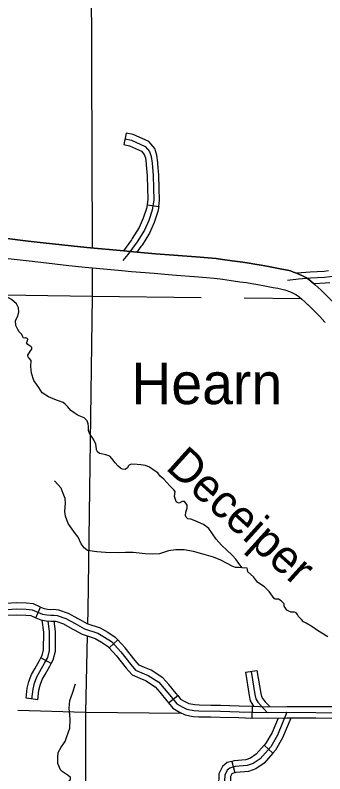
# Model space of a CAD drawing. Extents: x 813775 to 1157140, y 1757555 to 1979907.
# Drawn here: x 931113 to 939008, y 1842754 to 1862069 of the extents above; entities that cross this region are included whole.
import ezdxf

# ---------------------------------------------------------------- set-up
doc = ezdxf.new("R2010")
doc.units = 0
for name, color, linetype in [('Level 10', 7, 'Continuous'), ('Level 25', 7, 'Continuous'), ('Level 31', 7, 'Continuous'), ('Level 32', 7, 'Continuous'), ('Level 35', 7, 'Continuous'), ('Level 5', 7, 'Continuous')]:
    doc.layers.add(name, color=color, linetype=linetype)

msp = doc.modelspace()

# ---------------------------------------------------------------- linework, layer by layer
at = {"layer": 'Level 10'}
for p, q in [((938921, 1855062), (938925, 1855058)), ((938578, 1854698), (938573, 1854702)), ((939007, 1854249), (939009, 1854246))]:
    msp.add_line(p, q, dxfattribs=at)
for points in [[(930839, 1856390), (931449, 1856317), (931825, 1856276), (932539, 1856194), (932942, 1856153), (933881, 1856069), (934127, 1856042), (934695, 1855996), (935154, 1855959), (935828, 1855905), (936032, 1855891), (936236, 1855870), (936400, 1855851), (936643, 1855816), (936915, 1855778), (937082, 1855753), (937225, 1855731), (937384, 1855704), (937572, 1855672), (937782, 1855631), (937915, 1855605), (938054, 1855573), (938129, 1855557), (938206, 1855528), (938261, 1855509), (938345, 1855474), (938436, 1855434), (938519, 1855390), (938593, 1855344), (938663, 1855291), (938752, 1855216), (938832, 1855146), (938921, 1855062)], [(938921, 1855062), (938832, 1855146), (938752, 1855216), (938663, 1855291), (938593, 1855344), (938519, 1855390), (938436, 1855434), (938345, 1855474), (938261, 1855509), (938206, 1855528), (938129, 1855557), (938054, 1855573), (937915, 1855605), (937782, 1855631), (937572, 1855672), (937384, 1855704), (937225, 1855731), (937082, 1855753), (936915, 1855778), (936643, 1855816), (936400, 1855851), (936236, 1855870), (936032, 1855891), (935828, 1855905), (935154, 1855959), (934695, 1855996), (934127, 1856042), (933881, 1856069), (932942, 1856153), (932539, 1856194), (931825, 1856276), (931449, 1856317), (930839, 1856390)], [(930779, 1855894), (931393, 1855820), (931770, 1855779), (932485, 1855697), (932895, 1855655), (933831, 1855572), (934079, 1855544), (934655, 1855498), (935113, 1855461), (935791, 1855406), (935990, 1855392), (936183, 1855372), (936337, 1855355), (936573, 1855321), (936843, 1855283), (937007, 1855259), (937146, 1855237), (937301, 1855211), (937481, 1855181), (937687, 1855140), (937812, 1855116), (937946, 1855085), (937988, 1855076), (938035, 1855059), (938081, 1855042), (938147, 1855014), (938218, 1854983), (938269, 1854956), (938310, 1854931), (938350, 1854901), (938425, 1854837), (938496, 1854775), (938578, 1854698)], [(930779, 1855894), (931393, 1855820), (931770, 1855779), (932485, 1855697), (932895, 1855655), (933831, 1855572), (934079, 1855544), (934655, 1855498), (935113, 1855461), (935791, 1855406), (935990, 1855392), (936183, 1855372), (936337, 1855355), (936573, 1855321), (936843, 1855283), (937007, 1855259), (937146, 1855237), (937301, 1855211), (937481, 1855181), (937687, 1855140), (937812, 1855116), (937946, 1855085), (937988, 1855076), (938035, 1855059), (938081, 1855042), (938147, 1855014), (938218, 1854983), (938269, 1854956), (938310, 1854931), (938350, 1854901), (938425, 1854837), (938496, 1854775), (938578, 1854698)], [(938925, 1855058), (939060, 1854924), (939243, 1854735), (939380, 1854581)], [(939380, 1854581), (939243, 1854735), (939060, 1854924), (938925, 1855058)], [(938573, 1854702), (938704, 1854573), (938877, 1854395), (939007, 1854249)], [(938573, 1854702), (938704, 1854573), (938877, 1854395), (939007, 1854249)]]:
    msp.add_lwpolyline(points, dxfattribs=at)
at = {"layer": 'Level 31'}
for p, q in [((933945, 1859068), (933882, 1858775)), ((934475, 1857243), (934772, 1857198)), ((931642, 1846726), (931763, 1847001)), ((933729, 1846165), (933507, 1845962)), ((935023, 1844561), (935258, 1844747)), ((937154, 1844174), (937163, 1844474))]:
    msp.add_line(p, q, dxfattribs=at)
for points in [[(934754, 1858286), (934751, 1858316), (934727, 1858507), (934672, 1858676), (934522, 1858850), (934125, 1859029), (933945, 1859068)], [(933882, 1858775), (934031, 1858743), (934338, 1858604), (934405, 1858525), (934433, 1858441), (934453, 1858285), (934455, 1858261)], [(933914, 1858921), (934078, 1858886), (934430, 1858727), (934539, 1858600)], [(934539, 1858600), (934580, 1858474), (934602, 1858300), (934629, 1857985), (934637, 1857661), (934646, 1857372), (934606, 1857109), (934518, 1856843), (934407, 1856594), (934225, 1856301), (933985, 1855972), (933856, 1855821)], [(934455, 1858261), (934479, 1857977), (934488, 1857656), (934496, 1857381), (934475, 1857243)], [(934455, 1858261), (934479, 1857977), (934488, 1857656), (934496, 1857381), (934475, 1857243)], [(934772, 1857198), (934797, 1857363), (934787, 1857665), (934778, 1857993), (934754, 1858286)], [(934475, 1857243), (934460, 1857145), (934378, 1856897), (934274, 1856664), (934100, 1856384), (934077, 1856352)], [(934772, 1857198), (934753, 1857074), (934658, 1856788), (934539, 1856523), (934349, 1856217), (934319, 1856176)], [(934077, 1856352), (933871, 1856070)], [(934319, 1856176), (934216, 1856035)], [(939102, 1855556), (938990, 1855543), (938630, 1855527), (938292, 1855497)], [(939137, 1855258), (939014, 1855243), (938734, 1855231)], [(931763, 1847001), (931585, 1847079), (931406, 1847095), (931146, 1847104), (930887, 1847090), (930606, 1847025), (930571, 1846994)], [(931763, 1847001), (931852, 1846961), (931939, 1846947), (932025, 1846940), (932101, 1846944), (932219, 1846933), (932465, 1846847), (932712, 1846712), (932765, 1846683)], [(930748, 1846750), (930929, 1846792), (931149, 1846804), (931387, 1846795), (931510, 1846785), (931642, 1846726)], [(931642, 1846726), (931767, 1846671), (931902, 1846649), (932020, 1846639), (932095, 1846644), (932154, 1846638), (932343, 1846572), (932568, 1846449), (932621, 1846420)], [(932765, 1846683), (932944, 1846585), (933279, 1846474), (933474, 1846362), (933666, 1846233), (933729, 1846165)], [(932621, 1846420), (932824, 1846309), (933155, 1846199), (933315, 1846107), (933469, 1846004), (933507, 1845962)], [(934409, 1845464), (934274, 1845521), (934176, 1845637), (933917, 1845958), (933729, 1846165)], [(933507, 1845962), (933689, 1845763), (933945, 1845445), (934092, 1845273), (934292, 1845188)], [(935258, 1844747), (935215, 1844802), (935030, 1845027), (934877, 1845201), (934578, 1845392), (934409, 1845464)], [(934292, 1845188), (934437, 1845126), (934680, 1844971), (934802, 1844833), (934981, 1844614), (935023, 1844561)], [(935258, 1844747), (935331, 1844654), (935438, 1844592), (935540, 1844545), (935691, 1844515), (935806, 1844507), (936105, 1844502)], [(935023, 1844561), (935131, 1844424), (935299, 1844326), (935446, 1844258), (935651, 1844217), (935793, 1844207), (936100, 1844202)], [(936105, 1844502), (936349, 1844498), (936825, 1844485), (937163, 1844474)], [(937163, 1844474), (937541, 1844462), (938041, 1844471), (938215, 1844470)], [(938215, 1844470), (938783, 1844467), (939271, 1844464)], [(938215, 1844470), (938783, 1844467), (939271, 1844464)], [(936100, 1844202), (936342, 1844198), (936816, 1844185), (937154, 1844174)], [(938213, 1844170), (938043, 1844171), (937539, 1844162), (937154, 1844174)], [(939269, 1844164), (938781, 1844167), (938213, 1844170)]]:
    msp.add_lwpolyline(points, dxfattribs=at)
at = {"layer": 'Level 32'}
for p, q in [((932032, 1845564), (931769, 1845707)), ((936981, 1845339), (937277, 1845387)), ((931689, 1844639), (931391, 1844676)), ((937460, 1843480), (937685, 1843281)), ((936636, 1843071), (936713, 1842781))]:
    msp.add_line(p, q, dxfattribs=at)
for points in [[(939286, 1855426), (939002, 1855393), (938640, 1855377), (938340, 1855351), (938059, 1855317)], [(938042, 1844321), (938782, 1844317), (941144, 1844299), (941912, 1844282), (942387, 1844273), (942632, 1844277), (942991, 1844326), (943204, 1844424), (943342, 1844553), (943377, 1844624), (943457, 1844806), (943497, 1845006), (943524, 1845397), (943506, 1846339), (943440, 1847750), (943395, 1848563)], [(930908, 1846941), (931148, 1846954), (931396, 1846945), (931547, 1846932), (931809, 1846816), (931920, 1846798), (932022, 1846790), (932098, 1846794), (932187, 1846785), (932404, 1846710), (932640, 1846581), (932884, 1846447), (933217, 1846336), (933394, 1846234), (933568, 1846119), (933803, 1845861), (934060, 1845541), (934183, 1845397), (934507, 1845259), (934778, 1845086), (934916, 1844930), (935098, 1844708), (935231, 1844539), (935369, 1844459), (935493, 1844401), (935671, 1844366), (935799, 1844357), (936346, 1844348), (936821, 1844335), (937540, 1844312), (938042, 1844321)], [(931540, 1844658), (931571, 1844907), (931607, 1845058), (931669, 1845222), (931744, 1845355), (931864, 1845569), (931944, 1845715), (931989, 1845893), (931993, 1846369), (931959, 1846645)], [(931769, 1845707), (931803, 1845770), (931839, 1845912), (931843, 1846360), (931806, 1846665)], [(932032, 1845564), (932085, 1845660), (932138, 1845874), (932143, 1846377), (932110, 1846644)], [(931391, 1844676), (931423, 1844933), (931463, 1845101), (931533, 1845286), (931614, 1845429), (931733, 1845641), (931769, 1845707)], [(931689, 1844639), (931719, 1844880), (931751, 1845014), (931805, 1845158), (931875, 1845282), (931995, 1845496), (932032, 1845564)], [(936981, 1845339), (937077, 1844746), (937106, 1844608), (937188, 1844473)], [(937129, 1845363), (937225, 1844773), (937247, 1844664), (937302, 1844575), (937373, 1844490), (937460, 1844401), (937540, 1844312)], [(937277, 1845387), (937372, 1844801), (937389, 1844720), (937424, 1844663), (937484, 1844591), (937569, 1844504), (937576, 1844496)], [(937576, 1844496), (937605, 1844464)], [(938042, 1844321), (937797, 1843739), (937629, 1843444)], [(937814, 1844167), (937663, 1843806), (937506, 1843532), (937460, 1843480)], [(938141, 1844171), (937932, 1843673), (937751, 1843356), (937685, 1843281)], [(937460, 1843480), (937258, 1843251), (937112, 1843152), (936997, 1843112), (936693, 1843086), (936636, 1843071)], [(937629, 1843444), (937358, 1843137), (937180, 1843017), (937029, 1842964), (936719, 1842937), (936585, 1842902), (936519, 1842848), (936457, 1842720), (936443, 1842435), (936386, 1841706), (936390, 1841564), (936421, 1841489), (936474, 1841417), (936581, 1841377), (936763, 1841333), (936972, 1841302), (937229, 1841275), (937384, 1841222), (937472, 1841158)], [(937685, 1843281), (937458, 1843024), (937248, 1842882), (937061, 1842816), (936744, 1842789), (936713, 1842781)], [(936636, 1843071), (936516, 1843039), (936398, 1842944), (936308, 1842757), (936294, 1842445), (936258, 1841998)], [(936713, 1842781), (936654, 1842765), (936639, 1842753), (936605, 1842682), (936593, 1842426), (936557, 1841974)]]:
    msp.add_lwpolyline(points, dxfattribs=at)
at = {"layer": 'Level 35'}
for points in [[(931129, 1854165), (931123, 1854294), (931183, 1854406), (931210, 1854517), (931202, 1854621), (931150, 1854721), (931020, 1854830), (930881, 1854909), (930808, 1855015), (930691, 1855233), (930552, 1855641)], [(931520, 1853280), (931471, 1853333), (931444, 1853366), (931433, 1853415), (931501, 1853521), (931536, 1853564), (931539, 1853610), (931515, 1853635), (931468, 1853662), (931436, 1853684), (931403, 1853730), (931430, 1853776), (931433, 1853817), (931409, 1853850), (931379, 1853855), (931357, 1853847), (931316, 1853853), (931305, 1853891), (931278, 1853945), (931213, 1854010), (931183, 1854070), (931129, 1854165)], [(932335, 1852212), (932164, 1852265), (931966, 1852352), (931805, 1852453), (931713, 1852589), (931593, 1852766), (931531, 1852951), (931515, 1853125), (931520, 1853280)], [(932875, 1851821), (932748, 1851867), (932694, 1851894), (932615, 1851948), (932530, 1852008), (932454, 1852098), (932384, 1852168), (932335, 1852212)], [(933187, 1851025), (933166, 1851144), (933117, 1851255), (933076, 1851326), (933019, 1851405), (932981, 1851495), (932981, 1851598), (932978, 1851666), (932951, 1851737), (932875, 1851821)], [(934814, 1850333), (934750, 1850416), (934679, 1850462), (934538, 1850562), (934438, 1850601), (934318, 1850620), (934220, 1850628), (934068, 1850636), (934022, 1850614), (933997, 1850587), (933975, 1850546), (933918, 1850505), (933848, 1850513), (933796, 1850535), (933731, 1850592), (933660, 1850671), (933590, 1850777), (933527, 1850840), (933421, 1850878), (933266, 1850913), (933215, 1850954), (933187, 1851003), (933187, 1851025)], [(935700, 1849194), (935589, 1849234), (935516, 1849250), (935469, 1849288), (935459, 1849334), (935467, 1849419), (935502, 1849527), (935494, 1849590), (935461, 1849642), (935431, 1849685), (935380, 1849688), (935353, 1849682), (935293, 1849647), (935230, 1849669), (935206, 1849712), (935179, 1849818), (935192, 1849941), (935154, 1849984), (935054, 1850088), (934907, 1850254), (934814, 1850333)], [(932379, 1849434), (932396, 1849650), (932390, 1849762), (932336, 1849895), (932284, 1850031), (932113, 1850216)], [(934430, 1848357), (934121, 1848387), (933925, 1848387), (933737, 1848384), (933419, 1848387), (933194, 1848406), (932960, 1848444), (932870, 1848509), (932797, 1848613), (932716, 1848776), (932626, 1848896), (932563, 1848983), (932468, 1849127), (932395, 1849317), (932379, 1849434)], [(936903, 1848001), (936837, 1848071), (936736, 1848218), (936641, 1848324), (936510, 1848452), (936377, 1848574), (936241, 1848732), (936143, 1848863), (936048, 1848996), (935912, 1849099), (935700, 1849194)], [(937025, 1847992), (936903, 1848001), (936805, 1848003), (936726, 1848006), (936642, 1848042), (936498, 1848115), (936354, 1848191), (936169, 1848273), (935875, 1848357), (935658, 1848414), (935419, 1848458), (935207, 1848458), (935019, 1848428), (934791, 1848354), (934618, 1848349), (934430, 1848357)], [(937289, 1847634), (937188, 1847769), (937047, 1847897), (937036, 1847960), (937025, 1847992)], [(939085, 1846241), (938822, 1846402), (938678, 1846508), (938531, 1846592), (938460, 1846622), (938411, 1846685), (938333, 1846758), (938311, 1846807), (938276, 1846851), (938232, 1846867), (938148, 1846867), (938077, 1846900), (938042, 1846921), (938004, 1846970), (937968, 1847025), (937971, 1847079), (937939, 1847117), (937892, 1847161), (937830, 1847199), (937743, 1847199), (937713, 1847221), (937670, 1847275), (937585, 1847395), (937536, 1847449), (937471, 1847512), (937379, 1847574), (937289, 1847634)], [(932432, 1843702), (932503, 1843919), (932515, 1844134), (932503, 1844254), (932493, 1844413), (932510, 1844623), (932571, 1844807), (932654, 1845047)], [(932380, 1842514), (932407, 1842538), (932456, 1842560), (932507, 1842582), (932527, 1842626), (932525, 1842662), (932466, 1842711), (932390, 1842763), (932314, 1842809), (932268, 1842856), (932197, 1843020), (932197, 1843166), (932207, 1843294), (932285, 1843433), (932390, 1843575), (932432, 1843702)]]:
    msp.add_lwpolyline(points, dxfattribs=at)
at = {"layer": 'Level 5'}
for points in [[(933044, 1865537), (933073, 1856142)], [(933075, 1855639), (933077, 1854913)], [(926856, 1855011), (933077, 1854913)], [(933077, 1854913), (932964, 1846914), (932957, 1846581)], [(933077, 1854913), (935858, 1854883)], [(936951, 1854872), (938403, 1854856)], [(932951, 1846267), (932910, 1844326)], [(931181, 1844372), (932910, 1844326)], [(932910, 1844326), (932894, 1833694)], [(932910, 1844326), (935349, 1844297)]]:
    msp.add_lwpolyline(points, dxfattribs=at)

# ---------------------------------------------------------------- texts
at = {"layer": 'Level 25'}
msp.add_text('Hearn', height=1056, dxfattribs=at).set_placement((934075, 1852165))
at = {"layer": 'Level 35'}
msp.add_text('Deceiper', height=844.8, rotation=317.8565, dxfattribs=at).set_placement((934923, 1850525))

doc.saveas('drawing.dxf')
